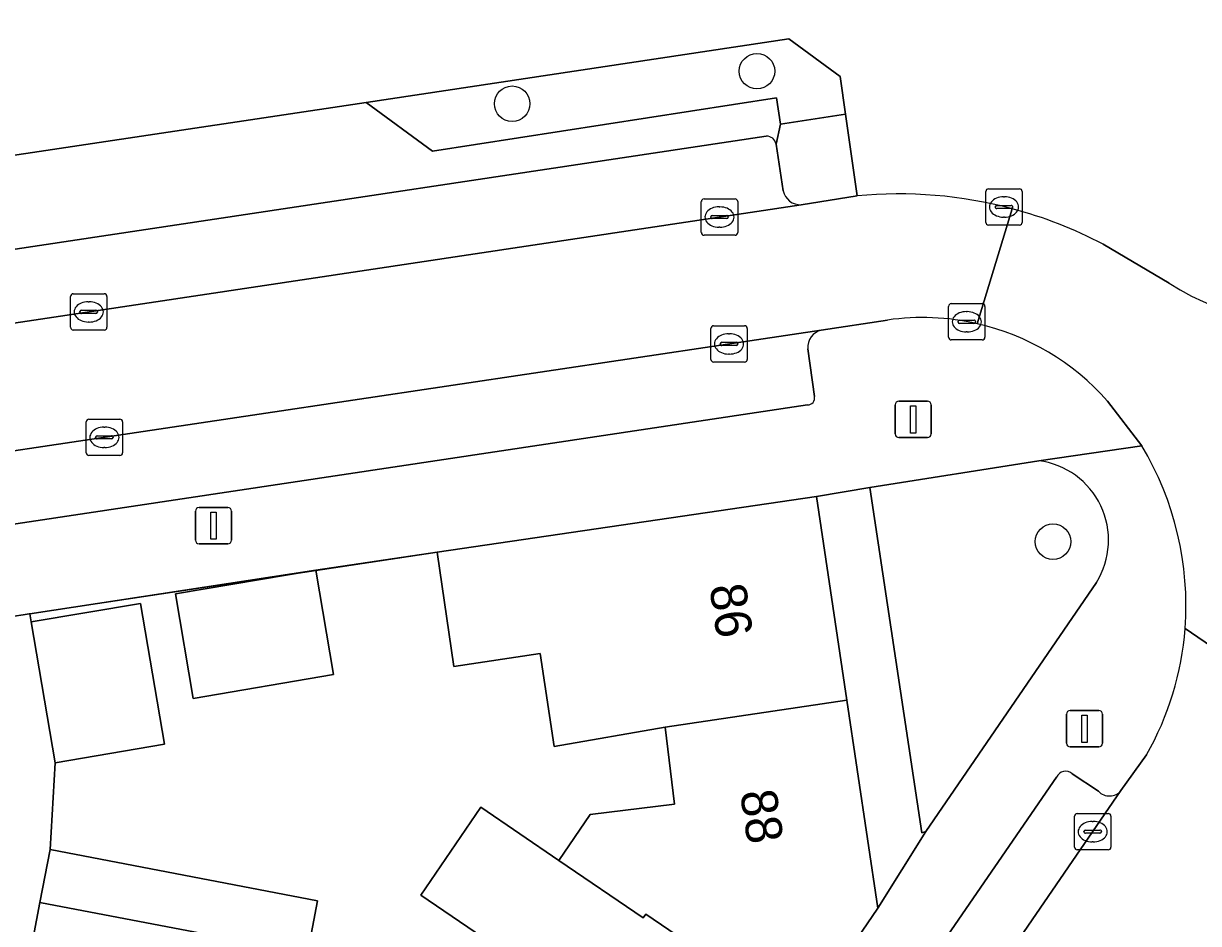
# Model space of a CAD drawing. Extents: x 159279 to 160377, y 384531 to 385888.
# Drawn here: x 159842.72 to 159875.06, y 384897.02 to 384921.8 of the extents above; entities that cross this region are included whole.
import ezdxf

# ---------------------------------------------------------------- set-up
doc = ezdxf.new("R2010")
doc.units = 0
for name, color, linetype in [('IMGEO_Boom', 7, 'Continuous'), ('IMGEO_Erf', 7, 'Continuous'), ('IMGEO_Groenvoorziening', 7, 'Continuous'), ('IMGEO_Haag', 7, 'Continuous'), ('IMGEO_Kolk', 7, 'Continuous'), ('IMGEO_Lichtmast', 7, 'Continuous'), ('IMGEO_Muur', 7, 'Continuous'), ('IMGEO_Pand', 7, 'Continuous'), ('IMGEO_Pand_nummerreeks', 7, 'Continuous'), ('IMGEO_Parkeervlak_open', 7, 'Continuous'), ('IMGEO_Rijbaan_lokaal_open', 7, 'Continuous'), ('IMGEO_Voetpad_open', 7, 'Continuous')]:
    doc.layers.add(name, color=color, linetype=linetype)

msp = doc.modelspace()

# ---------------------------------------------------------------- linework, layer by layer
at = {"layer": 'IMGEO_Boom'}
for centre in [(159862.906, 384920.484), (159856.17, 384919.589), (159871.051, 384907.532)]:
    msp.add_circle(centre, 0.489, dxfattribs=at)
at = {"layer": 'IMGEO_Erf'}
msp.add_lwpolyline([(159855.587, 384896.483), (159853.657, 384897.798), (159855.306, 384900.218), (159857.456, 384898.753), (159858.315, 384900.016), (159860.639, 384900.304), (159860.376, 384902.42), (159857.327, 384901.889), (159856.945, 384904.451), (159854.568, 384904.097), (159854.105, 384907.239), (159850.765, 384906.751), (159842.895, 384905.544), (159842.933, 384905.322), (159845.945, 384905.832), (159846.602, 384901.952), (159843.591, 384901.442), (159843.457, 384899.052), (159850.813, 384897.646), (159850.535, 384896.191)], dxfattribs=at)
msp.add_lwpolyline([(159850.765, 384906.751), (159851.253, 384903.87), (159847.396, 384903.217), (159846.908, 384906.098)], close=True, dxfattribs=at)
at = {"layer": 'IMGEO_Groenvoorziening'}
msp.add_lwpolyline([(159852.152, 384919.622), (159853.976, 384918.285), (159863.441, 384919.748), (159863.557, 384919.029), (159865.34, 384919.305), (159865.194, 384920.335), (159863.783, 384921.378)], close=True, dxfattribs=at)
for points in [[(159864.125, 384916.807), (159865.659, 384917.05), (159865.34, 384919.305), (159863.557, 384919.029), (159863.432, 384918.475), (159863.626, 384917.194)], [(159870.658, 384909.761), (159866.011, 384909.019), (159867.439, 384899.516), (159867.556, 384899.554), (159872.248, 384906.412)]]:
    msp.add_lwpolyline(points, dxfattribs=at)
for centre, radius, start, end in [((159864.103, 384917.294), 0.487, 191.8199, 272.5893), ((159870.376, 384907.575), 2.204, 328.1514, 82.6424)]:
    msp.add_arc(centre, radius, start, end, dxfattribs=at)
at = {"layer": 'IMGEO_Haag'}
msp.add_lwpolyline([(159852.152, 384919.622), (159853.976, 384918.285), (159863.441, 384919.748), (159863.557, 384919.029), (159865.34, 384919.305), (159865.194, 384920.335), (159863.783, 384921.378)], close=True, dxfattribs=at)
at = {"layer": 'IMGEO_Kolk'}
for p, q in [((159869.203, 384916.321), (159869.203, 384917.173)), ((159869.278, 384917.247), (159870.13, 384917.247)), ((159870.204, 384917.173), (159870.204, 384916.321)), ((159861.375, 384916.043), (159861.375, 384916.895)), ((159861.45, 384916.969), (159862.302, 384916.969)), ((159862.376, 384916.895), (159862.376, 384916.043)), ((159869.505, 384916.79), (159869.903, 384916.79)), ((159869.691, 384917.027), (159869.716, 384917.027)), ((159861.634, 384916.463), (159861.634, 384916.475)), ((159861.677, 384916.512), (159862.075, 384916.512)), ((159861.863, 384916.749), (159861.888, 384916.749)), ((159862.118, 384916.475), (159862.118, 384916.463)), ((159869.462, 384916.741), (159869.462, 384916.753)), ((159869.9, 384916.704), (159869.502, 384916.704)), ((159869.714, 384916.467), (159869.689, 384916.467)), ((159869.946, 384916.753), (159869.946, 384916.741)), ((159862.072, 384916.426), (159861.674, 384916.426)), ((159861.886, 384916.189), (159861.861, 384916.189)), ((159870.13, 384916.247), (159869.278, 384916.247)), ((159862.302, 384915.969), (159861.45, 384915.969)), ((159844.019, 384913.433), (159844.019, 384914.285)), ((159844.094, 384914.359), (159844.946, 384914.359)), ((159845.02, 384914.285), (159845.02, 384913.433)), ((159844.278, 384913.853), (159844.278, 384913.865)), ((159844.321, 384913.902), (159844.719, 384913.902)), ((159844.507, 384914.139), (159844.532, 384914.139)), ((159844.762, 384913.865), (159844.762, 384913.853)), ((159868.179, 384913.159), (159868.179, 384914.011)), ((159868.254, 384914.085), (159869.106, 384914.085)), ((159868.667, 384913.865), (159868.692, 384913.865)), ((159869.18, 384914.011), (159869.18, 384913.159)), ((159844.716, 384913.816), (159844.318, 384913.816)), ((159844.53, 384913.579), (159844.505, 384913.579)), ((159868.438, 384913.579), (159868.438, 384913.591)), ((159868.876, 384913.542), (159868.478, 384913.542)), ((159868.481, 384913.628), (159868.879, 384913.628)), ((159868.922, 384913.591), (159868.922, 384913.579)), ((159844.946, 384913.359), (159844.094, 384913.359)), ((159861.638, 384912.551), (159861.638, 384913.403)), ((159861.713, 384913.477), (159862.565, 384913.477)), ((159862.126, 384913.257), (159862.151, 384913.257)), ((159862.639, 384913.403), (159862.639, 384912.551)), ((159868.69, 384913.305), (159868.665, 384913.305)), ((159861.897, 384912.971), (159861.897, 384912.983)), ((159862.335, 384912.934), (159861.937, 384912.934)), ((159861.94, 384913.02), (159862.338, 384913.02)), ((159862.381, 384912.983), (159862.381, 384912.971)), ((159869.106, 384913.085), (159868.254, 384913.085)), ((159862.149, 384912.697), (159862.124, 384912.697)), ((159862.565, 384912.477), (159861.713, 384912.477)), ((159844.45, 384909.978), (159844.45, 384910.83)), ((159844.525, 384910.904), (159845.377, 384910.904)), ((159844.938, 384910.684), (159844.963, 384910.684)), ((159845.451, 384910.83), (159845.451, 384909.978)), ((159844.709, 384910.398), (159844.709, 384910.41)), ((159845.147, 384910.361), (159844.749, 384910.361)), ((159844.752, 384910.447), (159845.15, 384910.447)), ((159845.193, 384910.41), (159845.193, 384910.398)), ((159844.961, 384910.124), (159844.936, 384910.124)), ((159845.377, 384909.904), (159844.525, 384909.904)), ((159871.645, 384899.121), (159871.645, 384899.973)), ((159871.72, 384900.047), (159872.572, 384900.047)), ((159872.646, 384899.973), (159872.646, 384899.121)), ((159872.133, 384899.827), (159872.158, 384899.827)), ((159871.904, 384899.541), (159871.904, 384899.553)), ((159872.342, 384899.504), (159871.944, 384899.504)), ((159871.947, 384899.59), (159872.345, 384899.59)), ((159872.388, 384899.553), (159872.388, 384899.541)), ((159872.572, 384899.047), (159871.72, 384899.047)), ((159872.156, 384899.267), (159872.131, 384899.267))]:
    msp.add_line(p, q, dxfattribs=at)
for points in [[(159869.203, 384916.321), (159869.203, 384917.173)], [(159869.278, 384917.247), (159870.13, 384917.247)], [(159870.204, 384917.173), (159870.204, 384916.321)], [(159861.375, 384916.043), (159861.375, 384916.895)], [(159861.45, 384916.969), (159862.302, 384916.969)], [(159862.376, 384916.895), (159862.376, 384916.043)], [(159870.13, 384916.247), (159869.278, 384916.247)], [(159862.302, 384915.969), (159861.45, 384915.969)], [(159844.019, 384913.433), (159844.019, 384914.285)], [(159844.094, 384914.359), (159844.946, 384914.359)], [(159845.02, 384914.285), (159845.02, 384913.433)], [(159868.179, 384913.159), (159868.179, 384914.011)], [(159868.254, 384914.085), (159869.106, 384914.085)], [(159869.18, 384914.011), (159869.18, 384913.159)], [(159844.946, 384913.359), (159844.094, 384913.359)], [(159861.638, 384912.551), (159861.638, 384913.403)], [(159861.713, 384913.477), (159862.565, 384913.477)], [(159862.639, 384913.403), (159862.639, 384912.551)], [(159869.106, 384913.085), (159868.254, 384913.085)], [(159862.565, 384912.477), (159861.713, 384912.477)], [(159844.45, 384909.978), (159844.45, 384910.83)], [(159844.525, 384910.904), (159845.377, 384910.904)], [(159845.451, 384910.83), (159845.451, 384909.978)], [(159845.377, 384909.904), (159844.525, 384909.904)], [(159871.645, 384899.121), (159871.645, 384899.973)], [(159871.72, 384900.047), (159872.572, 384900.047)], [(159872.646, 384899.973), (159872.646, 384899.121)], [(159872.572, 384899.047), (159871.72, 384899.047)]]:
    msp.add_lwpolyline(points, dxfattribs=at)
for centre, radius, start, end in [((159869.28, 384917.171), 0.0765, 91.552, 178.448), ((159869.28, 384917.171), 0.0765, 91.552, 178.448), ((159870.128, 384917.171), 0.0765, 1.552, 88.448), ((159870.128, 384917.171), 0.0765, 1.552, 88.448), ((159861.452, 384916.893), 0.0765, 91.552, 178.448), ((159861.452, 384916.893), 0.0765, 91.552, 178.448), ((159862.3, 384916.893), 0.0765, 1.552, 88.448), ((159862.3, 384916.893), 0.0765, 1.552, 88.448), ((159869.502, 384916.75), 0.0403, 85.8775, 175.7526), ((159869.907, 384916.752), 0.0386, 1.7309, 96.639), ((159861.674, 384916.472), 0.0403, 85.8775, 175.7526), ((159861.671, 384916.462), 0.0366, 178.938, 274.7102), ((159862.075, 384916.469), 0.043, 264.8664, 352.4533), ((159862.079, 384916.474), 0.0386, 1.7309, 96.639), ((159869.499, 384916.74), 0.0366, 178.938, 274.7102), ((159869.903, 384916.747), 0.043, 264.8664, 352.4533), ((159869.28, 384916.323), 0.0765, 181.552, 268.448), ((159869.28, 384916.323), 0.0765, 181.552, 268.448), ((159870.128, 384916.323), 0.0765, 271.552, 358.448), ((159870.128, 384916.323), 0.0765, 271.552, 358.448), ((159861.452, 384916.045), 0.0765, 181.552, 268.448), ((159861.452, 384916.045), 0.0765, 181.552, 268.448), ((159862.3, 384916.045), 0.0765, 271.552, 358.448), ((159862.3, 384916.045), 0.0765, 271.552, 358.448), ((159844.096, 384914.283), 0.0765, 91.552, 178.448), ((159844.096, 384914.283), 0.0765, 91.552, 178.448), ((159844.944, 384914.283), 0.0765, 1.552, 88.448), ((159844.944, 384914.283), 0.0765, 1.552, 88.448), ((159844.318, 384913.862), 0.0403, 85.8775, 175.7526), ((159844.723, 384913.864), 0.0386, 1.7309, 96.639), ((159868.256, 384914.009), 0.0765, 91.552, 178.448), ((159868.256, 384914.009), 0.0765, 91.552, 178.448), ((159869.104, 384914.009), 0.0765, 1.552, 88.448), ((159869.104, 384914.009), 0.0765, 1.552, 88.448), ((159844.315, 384913.852), 0.0366, 178.938, 274.7102), ((159844.719, 384913.859), 0.043, 264.8664, 352.4533), ((159868.478, 384913.588), 0.0403, 85.8775, 175.7526), ((159868.475, 384913.578), 0.0366, 178.938, 274.7102), ((159868.879, 384913.585), 0.043, 264.8664, 352.4533), ((159868.883, 384913.59), 0.0386, 1.7309, 96.639), ((159844.096, 384913.435), 0.0765, 181.552, 268.448), ((159844.096, 384913.435), 0.0765, 181.552, 268.448), ((159844.944, 384913.435), 0.0765, 271.552, 358.448), ((159844.944, 384913.435), 0.0765, 271.552, 358.448), ((159861.715, 384913.401), 0.0765, 91.552, 178.448), ((159861.715, 384913.401), 0.0765, 91.552, 178.448), ((159862.563, 384913.401), 0.0765, 1.552, 88.448), ((159862.563, 384913.401), 0.0765, 1.552, 88.448), ((159861.937, 384912.98), 0.0403, 85.8775, 175.7526), ((159861.934, 384912.97), 0.0366, 178.938, 274.7102), ((159862.338, 384912.977), 0.043, 264.8664, 352.4533), ((159862.342, 384912.982), 0.0386, 1.7309, 96.639), ((159868.256, 384913.161), 0.0765, 181.552, 268.448), ((159868.256, 384913.161), 0.0765, 181.552, 268.448), ((159869.104, 384913.161), 0.0765, 271.552, 358.448), ((159869.104, 384913.161), 0.0765, 271.552, 358.448), ((159861.715, 384912.553), 0.0765, 181.552, 268.448), ((159861.715, 384912.553), 0.0765, 181.552, 268.448), ((159862.563, 384912.553), 0.0765, 271.552, 358.448), ((159862.563, 384912.553), 0.0765, 271.552, 358.448), ((159844.527, 384910.828), 0.0765, 91.552, 178.448), ((159844.527, 384910.828), 0.0765, 91.552, 178.448), ((159845.375, 384910.828), 0.0765, 1.552, 88.448), ((159845.375, 384910.828), 0.0765, 1.552, 88.448), ((159844.749, 384910.407), 0.0403, 85.8775, 175.7526), ((159844.746, 384910.397), 0.0366, 178.938, 274.7102), ((159845.15, 384910.404), 0.043, 264.8664, 352.4533), ((159845.154, 384910.409), 0.0386, 1.7309, 96.639), ((159844.527, 384909.98), 0.0765, 181.552, 268.448), ((159844.527, 384909.98), 0.0765, 181.552, 268.448), ((159845.375, 384909.98), 0.0765, 271.552, 358.448), ((159845.375, 384909.98), 0.0765, 271.552, 358.448), ((159871.722, 384899.971), 0.0765, 91.552, 178.448), ((159871.722, 384899.971), 0.0765, 91.552, 178.448), ((159872.57, 384899.971), 0.0765, 1.552, 88.448), ((159872.57, 384899.971), 0.0765, 1.552, 88.448), ((159871.944, 384899.55), 0.0403, 85.8775, 175.7526), ((159871.941, 384899.54), 0.0366, 178.938, 274.7102), ((159872.345, 384899.547), 0.043, 264.8664, 352.4533), ((159872.349, 384899.552), 0.0386, 1.7309, 96.639), ((159871.722, 384899.123), 0.0765, 181.552, 268.448), ((159871.722, 384899.123), 0.0765, 181.552, 268.448), ((159872.57, 384899.123), 0.0765, 271.552, 358.448), ((159872.57, 384899.123), 0.0765, 271.552, 358.448)]:
    msp.add_arc(centre, radius, start, end, dxfattribs=at)
for centre, major_axis, ratio, start_param, end_param in [((159869.69, 384916.747), (-0.387, 0.002), 0.722429, 4.712389, 7.853982), ((159869.715, 384916.747), (-0.39, 0.002), 0.717154, 1.570796, 4.712389), ((159861.862, 384916.469), (-0.387, 0.002), 0.722429, 4.712389, 7.853982), ((159861.887, 384916.469), (-0.39, 0.002), 0.717154, 1.570796, 4.712389), ((159844.506, 384913.859), (-0.387, 0.002), 0.722429, 4.712389, 7.853982), ((159844.531, 384913.859), (-0.39, 0.002), 0.717154, 1.570796, 4.712389), ((159868.666, 384913.585), (-0.387, 0.002), 0.722429, 4.712389, 7.853982), ((159868.691, 384913.585), (-0.39, 0.002), 0.717154, 1.570796, 4.712389), ((159862.125, 384912.977), (-0.387, 0.002), 0.722429, 4.712389, 7.853982), ((159862.15, 384912.977), (-0.39, 0.002), 0.717154, 1.570796, 4.712389), ((159844.937, 384910.404), (-0.387, 0.002), 0.722429, 4.712389, 7.853982), ((159844.962, 384910.404), (-0.39, 0.002), 0.717154, 1.570796, 4.712389), ((159872.132, 384899.547), (-0.387, 0.002), 0.722429, 4.712389, 7.853982), ((159872.157, 384899.547), (-0.39, 0.002), 0.717154, 1.570796, 4.712389)]:
    msp.add_ellipse(centre, major_axis=major_axis, ratio=ratio, start_param=start_param, end_param=end_param, dxfattribs=at)
at = {"layer": 'IMGEO_Lichtmast'}
for p, q in [((159866.708, 384910.498), (159866.708, 384911.298)), ((159866.708, 384911.298), (159866.708, 384910.498)), ((159866.808, 384911.398), (159867.598, 384911.398)), ((159867.598, 384911.398), (159866.808, 384911.398)), ((159867.698, 384911.298), (159867.698, 384910.498)), ((159867.698, 384910.498), (159867.698, 384911.298)), ((159867.598, 384910.398), (159866.808, 384910.398)), ((159866.808, 384910.398), (159867.598, 384910.398)), ((159847.455, 384907.573), (159847.455, 384908.373)), ((159847.455, 384908.373), (159847.455, 384907.573)), ((159847.555, 384908.473), (159848.345, 384908.473)), ((159848.345, 384908.473), (159847.555, 384908.473)), ((159848.445, 384908.373), (159848.445, 384907.573)), ((159848.445, 384907.573), (159848.445, 384908.373)), ((159848.345, 384907.473), (159847.555, 384907.473)), ((159847.555, 384907.473), (159848.345, 384907.473)), ((159871.523, 384902.881), (159872.313, 384902.881)), ((159872.313, 384902.881), (159871.523, 384902.881)), ((159871.423, 384901.981), (159871.423, 384902.781)), ((159871.423, 384902.781), (159871.423, 384901.981)), ((159872.413, 384902.781), (159872.413, 384901.981)), ((159872.413, 384901.981), (159872.413, 384902.781)), ((159872.313, 384901.881), (159871.523, 384901.881)), ((159871.523, 384901.881), (159872.313, 384901.881))]:
    msp.add_line(p, q, dxfattribs=at)
for points in [[(159867.128, 384911.273), (159867.278, 384911.273), (159867.278, 384910.523), (159867.128, 384910.523), (159867.128, 384911.273)], [(159847.875, 384908.348), (159848.025, 384908.348), (159848.025, 384907.598), (159847.875, 384907.598), (159847.875, 384908.348)], [(159871.843, 384902.756), (159871.993, 384902.756), (159871.993, 384902.006), (159871.843, 384902.006), (159871.843, 384902.756)]]:
    msp.add_lwpolyline(points, dxfattribs=at)
for centre, start, end in [((159866.808, 384911.298), 90, 180), ((159866.808, 384911.298), 90, 180), ((159867.598, 384911.298), 0, 90), ((159867.598, 384911.298), 360, 90), ((159866.808, 384910.498), 180, 270), ((159866.808, 384910.498), 180, 270), ((159867.598, 384910.498), 270, 0), ((159867.598, 384910.498), 270, 0), ((159847.555, 384908.373), 90, 180), ((159847.555, 384908.373), 90, 180), ((159848.345, 384908.373), 0, 90), ((159848.345, 384908.373), 360, 90), ((159847.555, 384907.573), 180, 270), ((159847.555, 384907.573), 180, 270), ((159848.345, 384907.573), 270, 0), ((159848.345, 384907.573), 270, 0), ((159871.523, 384902.781), 90, 180), ((159871.523, 384902.781), 90, 180), ((159872.313, 384902.781), 0, 90), ((159872.313, 384902.781), 360, 90), ((159871.523, 384901.981), 180, 270), ((159871.523, 384901.981), 180, 270), ((159872.313, 384901.981), 270, 0), ((159872.313, 384901.981), 270, 0)]:
    msp.add_arc(centre, 0.1, start, end, dxfattribs=at)
at = {"layer": 'IMGEO_Muur'}
msp.add_lwpolyline([(159842.883, 384905.542), (159854.105, 384907.239)], dxfattribs=at)
at = {"layer": 'IMGEO_Pand'}
for points in [[(159864.542, 384908.773), (159854.105, 384907.239), (159854.568, 384904.097), (159856.945, 384904.451), (159857.327, 384901.889), (159860.376, 384902.42), (159865.376, 384903.166)], [(159850.765, 384906.751), (159846.908, 384906.098), (159847.396, 384903.217), (159851.253, 384903.87)], [(159842.933, 384905.322), (159843.591, 384901.442), (159846.602, 384901.952), (159845.945, 384905.832)], [(159865.376, 384903.166), (159860.376, 384902.42), (159860.639, 384900.304), (159858.315, 384900.016), (159857.456, 384898.753), (159859.775, 384897.173), (159859.846, 384897.277), (159864.13, 384894.359), (159866.228, 384897.439)], [(159859.846, 384897.277), (159859.775, 384897.173), (159857.456, 384898.753), (159855.306, 384900.218), (159853.657, 384897.798), (159855.587, 384896.483), (159854.078, 384894.268), (159856.612, 384892.542), (159860.902, 384889.62), (159864.13, 384894.359)], [(159843.457, 384899.052), (159843.178, 384897.596), (159850.535, 384896.191), (159850.813, 384897.646)], [(159843.178, 384897.596), (159842.9, 384896.141), (159850.257, 384894.735), (159850.535, 384896.191)]]:
    msp.add_lwpolyline(points, close=True, dxfattribs=at)
at = {"layer": 'IMGEO_Parkeervlak_open'}
for points in [[(159863.162, 384918.694), (159844.016, 384915.81), (159801.678, 384909.433)], [(159863.626, 384917.194), (159863.432, 384918.475)], [(159801.309, 384907.363), (159825.463, 384910.995), (159828.051, 384911.384), (159864.125, 384916.807)], [(159864.675, 384913.357), (159828.584, 384907.954), (159825.995, 384907.567), (159824.727, 384907.377)], [(159864.486, 384911.528), (159864.305, 384912.843)], [(159825.668, 384905.493), (159864.301, 384911.295)], [(159871.149, 384901.051), (159862.663, 384888.7), (159854.183, 384876.035)], [(159872.305, 384900.658), (159871.581, 384901.139)], [(159853.991, 384872.729), (159864.145, 384887.869), (159872.922, 384900.679)]]:
    msp.add_lwpolyline(points, dxfattribs=at)
for centre, radius, start, end in [((159863.175, 384918.434), 0.261, 9.1097, 92.7985), ((159864.103, 384917.294), 0.487, 191.8199, 272.5893), ((159864.798, 384912.878), 0.495, 104.4547, 184.0493), ((159864.3, 384911.486), 0.191, 270.4356, 12.6658), ((159871.396, 384900.945), 0.268, 46.2829, 156.7448), ((159872.604, 384900.943), 0.413, 223.5965, 320.3022)]:
    msp.add_arc(centre, radius, start, end, dxfattribs=at)
at = {"layer": 'IMGEO_Rijbaan_lokaal_open'}
for points in [[(159874.688, 384905.142), (159879.386, 384901.926), (159879.933, 384902.757), (159886.025, 384911.69), (159886.985, 384913.101), (159889.452, 384916.724), (159889.608, 384916.953), (159892.317, 384920.935), (159895.245, 384925.237)], [(159865.659, 384917.05), (159864.125, 384916.807), (159828.051, 384911.384), (159828.584, 384907.954), (159864.675, 384913.357), (159866.501, 384913.634)], [(159868.968, 384913.533), (159869.928, 384916.698)], [(159869.928, 384916.698), (159868.968, 384913.533)], [(159874.25, 384914.647), (159872.431, 384915.719)], [(159872.55, 384911.403), (159873.494, 384910.171)], [(159874.043, 384894.048), (159879.386, 384901.926), (159874.688, 384905.142)], [(159873.627, 384901.661), (159872.922, 384900.679), (159864.145, 384887.869)]]:
    msp.add_lwpolyline(points, dxfattribs=at)
for centre, radius, start, end in [((159866.818, 384905.041), 12.065, 75.0607, 95.5119), ((159866.847, 384905.132), 11.97, 62.1919, 75.0841), ((159878.093, 384920.645), 7.123, 237.3492, 325.0498), ((159867.462, 384906.937), 6.766, 77.1417, 98.1695), ((159867.463, 384906.924), 6.778, 41.3581, 77.1671), ((159866.159, 384905.773), 8.552, 355.7664, 30.9457), ((159866.345, 384905.783), 8.367, 330.489, 355.6088)]:
    msp.add_arc(centre, radius, start, end, dxfattribs=at)
at = {"layer": 'IMGEO_Voetpad_open'}
for points in [[(159798.551, 384908.751), (159798.685, 384909.282), (159798.589, 384909.986), (159798.581, 384910.041), (159799.852, 384911.749), (159811.279, 384913.48), (159812.498, 384913.664), (159817.446, 384914.412), (159819.711, 384914.754), (159824.099, 384915.408), (159825.49, 384915.597), (159830.534, 384916.379), (159852.152, 384919.622), (159863.783, 384921.378), (159865.194, 384920.335), (159865.34, 384919.305), (159865.659, 384917.05)], [(159863.432, 384918.475), (159863.557, 384919.029), (159863.441, 384919.748), (159853.976, 384918.285), (159852.152, 384919.622), (159830.534, 384916.379), (159829.186, 384914.57), (159825.714, 384914.039), (159825.49, 384915.597), (159824.099, 384915.408), (159824.318, 384913.838), (159818.426, 384912.968), (159819.711, 384914.754), (159817.446, 384914.412), (159812.498, 384913.664), (159811.279, 384913.48), (159810.008, 384911.692), (159801.113, 384910.355), (159801.186, 384909.656), (159801.486, 384909.183)], [(159801.678, 384909.433), (159844.016, 384915.81), (159863.162, 384918.694)], [(159872.431, 384915.719), (159874.25, 384914.647)], [(159866.501, 384913.634), (159864.675, 384913.357)], [(159864.305, 384912.843), (159864.486, 384911.528)], [(159798.289, 384898.905), (159803.564, 384899.689), (159808.787, 384900.464), (159813.951, 384901.231), (159819.36, 384902.035), (159825.377, 384902.95), (159825.86, 384903.003), (159837.771, 384904.785), (159840.835, 384905.243), (159841.464, 384905.335), (159842.713, 384905.517), (159842.883, 384905.542), (159842.895, 384905.544), (159850.765, 384906.751), (159854.105, 384907.239), (159864.542, 384908.773), (159866.011, 384909.019), (159870.658, 384909.761), (159873.494, 384910.171), (159872.55, 384911.403)], [(159864.301, 384911.295), (159825.668, 384905.493)], [(159873.494, 384910.171), (159870.658, 384909.761)], [(159872.248, 384906.412), (159867.556, 384899.554), (159866.228, 384897.439), (159864.13, 384894.359)], [(159842.9, 384896.141), (159843.178, 384897.596), (159843.457, 384899.052), (159843.591, 384901.442), (159842.933, 384905.322), (159842.895, 384905.544), (159842.883, 384905.542), (159842.713, 384905.517), (159841.464, 384905.335), (159841.591, 384904.46), (159842.032, 384901.442), (159841.787, 384900.411), (159841.555, 384899.435), (159840.533, 384895.132)], [(159872.922, 384900.679), (159873.627, 384901.661)], [(159854.183, 384876.035), (159862.663, 384888.7), (159871.149, 384901.051)], [(159871.581, 384901.139), (159872.305, 384900.658)]]:
    msp.add_lwpolyline(points, dxfattribs=at)
msp.add_lwpolyline([(159866.011, 384909.019), (159864.542, 384908.773), (159865.376, 384903.166), (159866.228, 384897.439), (159867.556, 384899.554), (159867.439, 384899.516)], close=True, dxfattribs=at)
for centre, radius, start, end in [((159863.175, 384918.434), 0.261, 9.1097, 92.7985), ((159866.818, 384905.041), 12.065, 75.0607, 95.5119), ((159866.847, 384905.132), 11.97, 62.1919, 75.0841), ((159878.093, 384920.645), 7.123, 237.3492, 325.0498), ((159867.462, 384906.937), 6.766, 77.1417, 98.1695), ((159867.463, 384906.924), 6.778, 41.3581, 77.1671), ((159864.798, 384912.878), 0.495, 104.4547, 184.0493), ((159864.3, 384911.486), 0.191, 270.4356, 12.6658), ((159866.159, 384905.773), 8.552, 355.7664, 30.9457), ((159870.376, 384907.575), 2.204, 328.1514, 82.6424), ((159866.345, 384905.783), 8.367, 330.489, 355.6088), ((159871.396, 384900.945), 0.268, 46.2829, 156.7448), ((159872.604, 384900.943), 0.413, 223.5965, 320.3022)]:
    msp.add_arc(centre, radius, start, end, dxfattribs=at)

# ---------------------------------------------------------------- texts
at = {"layer": 'IMGEO_Pand_nummerreeks'}
for s, p in [('86', (159861.594, 384906.305)), ('88', (159862.437, 384900.635))]:
    msp.add_text(s, height=1, rotation=278.4624, dxfattribs=at).set_placement(p)

doc.saveas('drawing.dxf')
